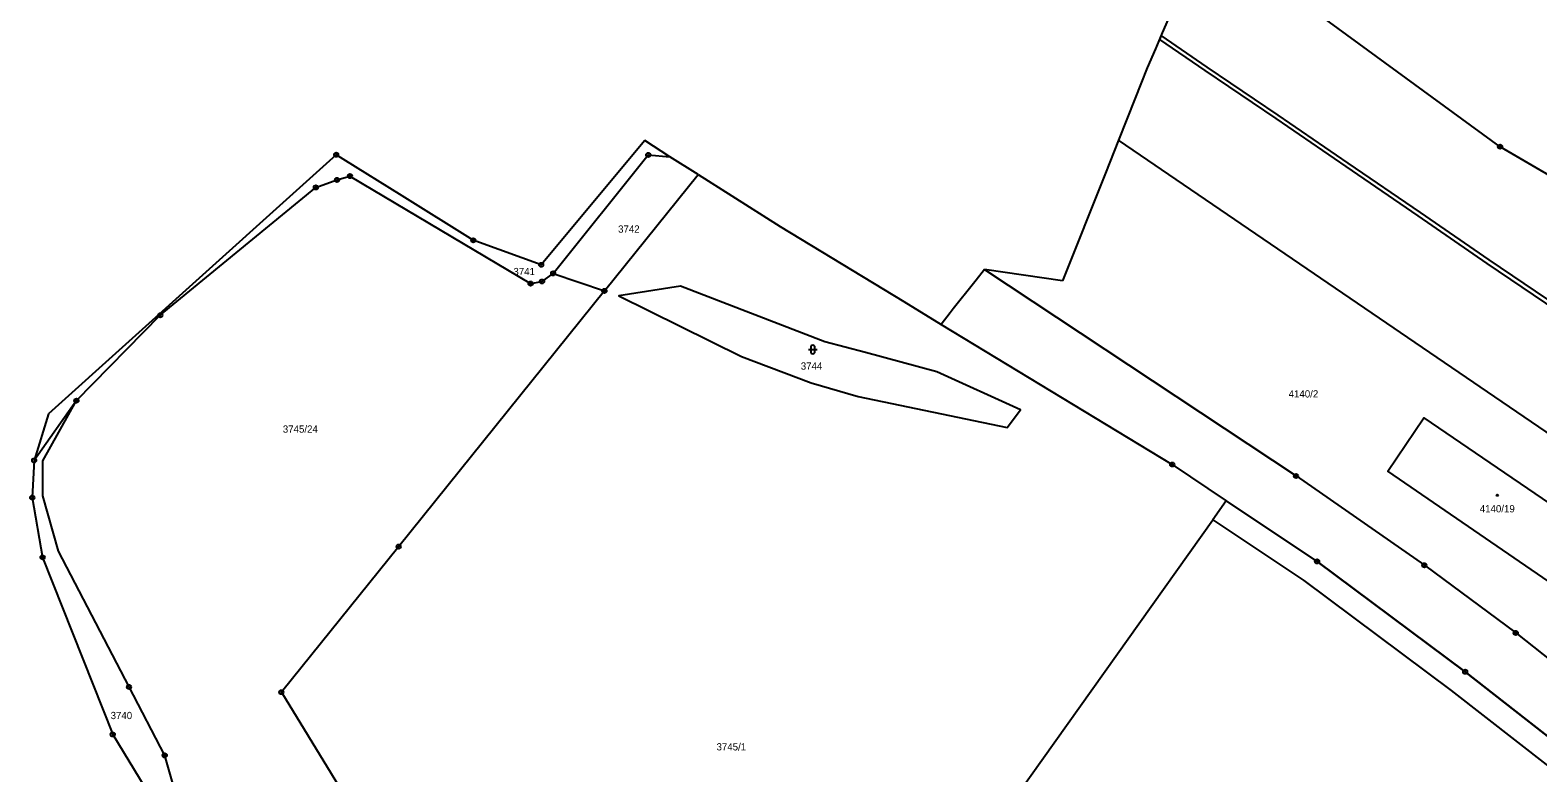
# Model space of a CAD drawing. Extents: x -644096 to -634268, y -1141430 to -1133463.
# Drawn here: x -641541.6 to -641187.5, y -1136892.5 to -1136718.2 of the extents above; entities that cross this region are included whole.
import ezdxf

# ---------------------------------------------------------------- set-up
doc = ezdxf.new("R2010")
doc.units = 0
for name, color, linetype in [('_CIVIL_CONSTRUCTION', 7, 'Continuous'), ('B_Hranice _3D', 7, 'Continuous'), ('M_Svah_Zarez', 7, 'Continuous'), ('svrsek_osa_sjezdy', 7, 'Continuous'), ('svrsek_osa_VRT', 7, 'Continuous'), ('terminal_VRT', 7, 'Continuous')]:
    doc.layers.add(name, color=color, linetype=linetype)

msp = doc.modelspace()

# ---------------------------------------------------------------- linework, layer by layer
at = {"layer": '_CIVIL_CONSTRUCTION'}
for centre, radius in [((-641196.36, -1136745.52), 0.5), ((-641196.36, -1136745.52), 0.0303), ((-641469.74, -1136747.42), 0.5), ((-641469.74, -1136747.42), 0.0303), ((-641396.45, -1136747.45), 0.5), ((-641396.45, -1136747.45), 0.0303), ((-641469.55, -1136753.31), 0.5), ((-641469.55, -1136753.31), 0.0303), ((-641466.5, -1136752.41), 0.5), ((-641466.5, -1136752.41), 0.0303), ((-641474.52, -1136755.08), 0.5), ((-641474.52, -1136755.08), 0.0303), ((-641437.53, -1136767.49), 0.5), ((-641437.53, -1136767.49), 0.0303), ((-641421.59, -1136773.24), 0.5), ((-641421.59, -1136773.24), 0.0303), ((-641418.78, -1136775.26), 0.5), ((-641424.07, -1136777.64), 0.5), ((-641424.07, -1136777.64), 0.0303), ((-641421.38, -1136777.15), 0.5), ((-641421.38, -1136777.15), 0.0303), ((-641418.78, -1136775.26), 0.0303), ((-641406.74, -1136779.36), 0.5), ((-641406.74, -1136779.36), 0.0303), ((-641511.05, -1136785.07), 0.5), ((-641511.05, -1136785.07), 0.0303), ((-641530.75, -1136805.12), 0.5), ((-641530.75, -1136805.12), 0.0303), ((-641540.68, -1136819.16), 0.5), ((-641540.68, -1136819.16), 0.0303), ((-641273.37, -1136820.11), 0.5), ((-641273.37, -1136820.11), 0.0303), ((-641244.29, -1136822.8), 0.5), ((-641244.29, -1136822.8), 0.0303), ((-641541.12, -1136827.88), 0.5), ((-641541.12, -1136827.88), 0.0303), ((-641538.7, -1136841.9), 0.5), ((-641538.7, -1136841.9), 0.0303), ((-641455.06, -1136839.36), 0.5), ((-641455.06, -1136839.36), 0.0303), ((-641239.35, -1136842.84), 0.5), ((-641239.35, -1136842.84), 0.0303), ((-641214.15, -1136843.74), 0.5), ((-641214.15, -1136843.74), 0.0303), ((-641192.68, -1136859.63), 0.5), ((-641192.68, -1136859.63), 0.0303), ((-641204.56, -1136868.74), 0.5), ((-641204.56, -1136868.74), 0.0303), ((-641518.4, -1136872.3), 0.5), ((-641518.4, -1136872.3), 0.0303), ((-641482.62, -1136873.54), 0.5), ((-641482.62, -1136873.54), 0.0303), ((-641522.21, -1136883.47), 0.5), ((-641522.21, -1136883.47), 0.0303), ((-641510, -1136888.38), 0.5), ((-641510, -1136888.38), 0.0303)]:
    msp.add_circle(centre, radius, dxfattribs=at)
at = {"layer": 'B_Hranice _3D'}
msp.add_lwpolyline([(-641182.45, -1136783.17), (-641198.94, -1136772.09), (-641215.09, -1136760.93), (-641232.05, -1136749.35), (-641248.5, -1136738.1), (-641265.13, -1136726.85), (-641275.95, -1136719.4), (-641276.35, -1136720.34), (-641265.69, -1136727.67), (-641249.06, -1136738.92), (-641232.61, -1136750.17), (-641215.65, -1136761.75), (-641199.5, -1136772.91), (-641183.01, -1136784.01)], dxfattribs=at)
msp.add_lwpolyline([(-641263.85, -1136833.08), (-641242.49, -1136847.34), (-641207.87, -1136873.11), (-641177.38, -1136896.86), (-641139.48, -1136925.67), (-641106.26, -1136952.5), (-641103.94, -1136947.21), (-641136.12, -1136921.34), (-641174.07, -1136892.51), (-641204.56, -1136868.74), (-641239.35, -1136842.84), (-641260.66, -1136828.6)], close=True, dxfattribs=at)
at = {"layer": 'M_Svah_Zarez'}
msp.add_circle((-641197.02, -1136827.32), 0.175, dxfattribs=at)
at = {"layer": 'svrsek_osa_sjezdy'}
for p, q in [((-641358.29, -1136792.6), (-641358.29, -1136793.6)), ((-641357.29, -1136793.6), (-641357.29, -1136792.6)), ((-641358.79, -1136793.1), (-641356.79, -1136793.1))]:
    msp.add_line(p, q, dxfattribs=at)
for centre, start, end in [((-641357.79, -1136792.6), 0, 180), ((-641357.79, -1136793.6), 180, 359.9879)]:
    msp.add_arc(centre, 0.5, start, end, dxfattribs=at)
at = {"layer": 'terminal_VRT'}
for p, q in [((-641282.07, -1136734.17), (-641285.97, -1136743.98)), ((-641391.38, -1136747.87), (-641397.24, -1136744.07)), ((-641285.97, -1136743.98), (-641289.05, -1136751.71)), ((-641469.74, -1136747.42), (-641481.47, -1136757.97)), ((-641384.75, -1136752.06), (-641391.38, -1136747.87)), ((-641406.74, -1136779.36), (-641384.75, -1136752.06)), ((-641289.05, -1136751.71), (-641299.13, -1136777.01)), ((-641437.53, -1136767.49), (-641454.24, -1136757.08)), ((-641481.47, -1136757.97), (-641537.32, -1136808.24)), ((-641299.13, -1136777.01), (-641317.44, -1136774.35)), ((-641418.78, -1136775.26), (-641406.74, -1136779.36)), ((-641336.4, -1136781.88), (-641327.67, -1136787.21)), ((-641530.75, -1136805.12), (-641540.68, -1136819.16)), ((-641537.32, -1136808.24), (-641540.68, -1136819.16)), ((-641540.68, -1136819.16), (-641541.12, -1136827.88)), ((-641541.12, -1136827.88), (-641538.7, -1136841.9))]:
    msp.add_line(p, q, dxfattribs=at)
for points in [[(-641265.5, -1136695.04), (-641271.16, -1136708.25), (-641272.38, -1136711.09), (-641275.7, -1136718.82), (-641277.3, -1136722.55), (-641279.22, -1136727.02), (-641280.72, -1136730.79), (-641282.07, -1136734.17)], [(-641021.98, -1136861.78), (-641026.53, -1136860.06), (-641070.93, -1136818.59), (-641196.36, -1136745.52), (-641265.5, -1136695.04)], [(-641397.24, -1136744.07), (-641421.59, -1136773.24), (-641436.08, -1136768.01), (-641437.53, -1136767.49)], [(-641146.48, -1136839.16), (-641173.71, -1136820.5), (-641285.97, -1136743.98)], [(-641454.24, -1136757.08), (-641468.08, -1136748.45), (-641469.74, -1136747.42)], [(-641418.78, -1136775.26), (-641396.45, -1136747.45), (-641391.38, -1136747.87)], [(-641530.75, -1136805.12), (-641511.05, -1136785.07), (-641474.52, -1136755.08), (-641469.55, -1136753.31), (-641466.5, -1136752.41), (-641424.07, -1136777.64), (-641421.38, -1136777.15), (-641418.78, -1136775.26)], [(-641384.75, -1136752.06), (-641376.82, -1136757.06), (-641365.45, -1136764.24), (-641336.4, -1136781.88)], [(-641317.44, -1136774.35), (-641319.43, -1136776.85), (-641320.04, -1136777.62), (-641324.79, -1136783.59), (-641325.52, -1136784.51), (-641327.67, -1136787.21)], [(-641317.44, -1136774.35), (-641244.29, -1136822.8), (-641214.15, -1136843.74), (-641192.68, -1136859.63), (-641156.38, -1136888.32), (-641133.9, -1136905.19), (-641094.12, -1136936.74)], [(-641358.16, -1136800.95), (-641347.15, -1136804.11), (-641312.14, -1136811.45), (-641308.98, -1136807.26), (-641328.69, -1136798.34), (-641345.4, -1136793.83), (-641354.96, -1136791.32), (-641388.86, -1136778.22), (-641403.38, -1136780.51), (-641374.54, -1136794.76), (-641358.16, -1136800.95)], [(-641406.74, -1136779.36), (-641455.06, -1136839.36), (-641482.62, -1136873.54), (-641464.69, -1136902.9)], [(-641327.67, -1136787.21), (-641273.37, -1136820.11), (-641260.66, -1136828.6), (-641239.35, -1136842.84), (-641204.56, -1136868.74), (-641174.07, -1136892.51), (-641136.12, -1136921.34), (-641103.94, -1136947.21)], [(-641507.8, -1136896.05), (-641510, -1136888.38), (-641518.4, -1136872.3), (-641534.99, -1136840.43), (-641538.67, -1136827.46), (-641538.66, -1136819.26), (-641530.75, -1136805.12)], [(-641170.96, -1136838.64), (-641179.58, -1136851.27), (-641222.76, -1136821.67), (-641214.28, -1136809.16), (-641170.96, -1136838.64)], [(-641326.4, -1136920.98), (-641263.85, -1136833.08), (-641242.49, -1136847.34), (-641207.87, -1136873.11), (-641177.38, -1136896.86), (-641139.48, -1136925.67), (-641106.26, -1136952.5)], [(-641538.7, -1136841.9), (-641522.21, -1136883.47), (-641508.47, -1136905.99)]]:
    msp.add_lwpolyline(points, dxfattribs=at)

# ---------------------------------------------------------------- texts
at = {"layer": 'svrsek_osa_VRT'}
for s, p in [('3742', (-641403.52, -1136765.7)), ('3741', (-641428.11, -1136775.67)), ('3744', (-641360.61, -1136797.84)), ('4140/2', (-641246.02, -1136804.38)), ('3745/24', (-641482.27, -1136812.64)), ('4140/19', (-641201.13, -1136831.34)), ('3740', (-641522.72, -1136879.86)), ('3745/1', (-641380.4, -1136887.21))]:
    msp.add_text(s, height=1.7, dxfattribs=at).set_placement(p)

doc.saveas('drawing.dxf')
